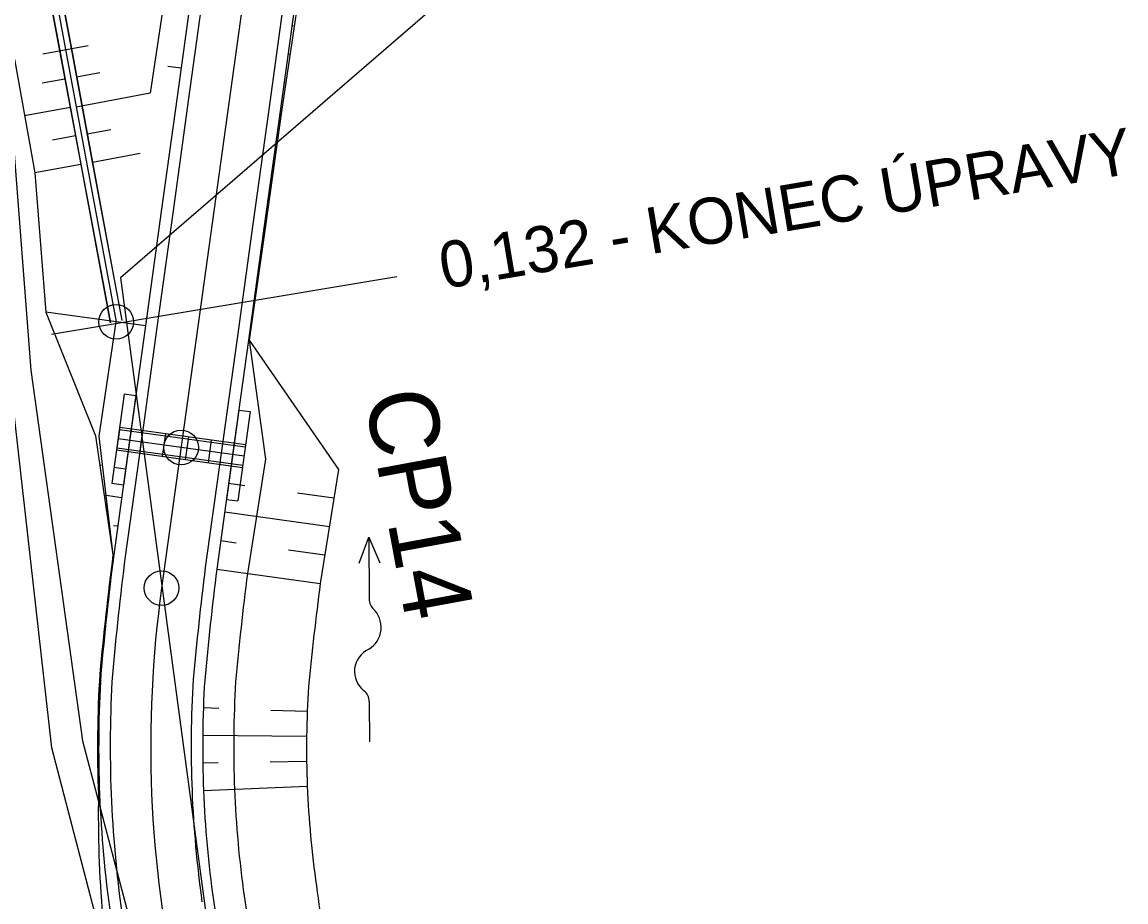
# Model space of a CAD drawing. Extents: x -495905 to -478420, y -1113297 to -1107716.
# Drawn here: x -481617.19 to -481569.44, y -1112652.71 to -1112614.65 of the extents above; entities that cross this region are included whole.
import ezdxf

# ---------------------------------------------------------------- set-up
doc = ezdxf.new("R2010")
doc.units = 0
for name, color, linetype in [('03_PC_OBJEKTY_NÁVRH_PR', 7, 'Continuous'), ('C11_HATCH_SLOPE_L', 7, 'Continuous'), ('C11_HATCH_SLOPE_R', 7, 'Continuous'), ('C11_HECTOMETRY', 7, 'Continuous'), ('C11_HLBODY', 7, 'Continuous'), ('C11_HRANA_TELESO', 7, 'Continuous'), ('C11_KORUNA', 7, 'Continuous'), ('C11_OSA', 7, 'Continuous'), ('C11_PRIKOP', 7, 'Continuous'), ('C11_VOZOVKA', 7, 'Continuous'), ('C11_ZPEVKRAJ', 7, 'Continuous'), ('CP14_HATCH_SLOPE_L', 7, 'Continuous'), ('CP14_HATCH_SLOPE_R', 7, 'Continuous'), ('CP14_HLBODY', 7, 'Continuous'), ('CP14_HRANA_TELESO', 7, 'Continuous'), ('CP14_KORUNA', 7, 'Continuous'), ('CP14_OSA', 7, 'Continuous'), ('CP14_STANICENI', 7, 'Continuous'), ('CP14_VOZOVKA', 7, 'Continuous'), ('CP14_ZPEVKRAJ', 7, 'Continuous'), ('DRENÁŽ', 7, 'Continuous'), ('Implicitní', 7, 'Continuous'), ('ODVODNĚNÍ PLOŠNÉ', 7, 'Continuous'), ('PLYN', 7, 'Continuous'), ('PROPUSTEK', 7, 'Continuous'), ('zamereni', 7, 'Continuous')]:
    doc.layers.add(name, color=color, linetype=linetype)

# ---------------------------------------------------------------- blocks, each defined once
blk = doc.blocks.new('A$C70B')
at = {"layer": 'DRENÁŽ'}
for p, q in [((0.869, 0.002), (-0.869, -0.002)), ((6.861, 0.426), (7.971, -0.002)), ((7.971, -0.002), (5.275, -0.002)), ((7.971, -0.002), (6.862, -0.478))]:
    blk.add_line(p, q, dxfattribs=at)
for centre, radius, start, end in [((2.168, -0.416), 1.055, 24.4039, 142.0836), ((0.872, 0.584), 0.582, 269.6924, 322.7901), ((4.08, 0.589), 1.109, 210.8873, 317.3707), ((5.319, -0.636), 0.636, 85.9766, 131.7248)]:
    blk.add_arc(centre, radius, start, end, dxfattribs=at)

msp = doc.modelspace()

# ---------------------------------------------------------------- linework, layer by layer
at = {"layer": 'C11_HATCH_SLOPE_L'}
for p, q in [((-481605.507, -1112614.794), (-481605.458, -1112614.801)), ((-481605.408, -1112614.808), (-481605.408, -1112614.808)), ((-481605.679, -1112616.032), (-481605.594, -1112616.044)), ((-481605.85, -1112617.271), (-481605.815, -1112617.276)), ((-481605.78, -1112617.28), (-481605.78, -1112617.28)), ((-481606.022, -1112618.509), (-481605.966, -1112618.516)), ((-481606.879, -1112624.7), (-481606.858, -1112624.702)), ((-481606.838, -1112624.705), (-481606.838, -1112624.705)), ((-481607.051, -1112625.938), (-481607.011, -1112625.943)), ((-481607.222, -1112627.176), (-481607.204, -1112627.178)), ((-481607.185, -1112627.181), (-481607.185, -1112627.181)), ((-481607.394, -1112628.414), (-481607.359, -1112628.419)), ((-481608.252, -1112634.605), (-481607.555, -1112634.702)), ((-481605.277, -1112635.017), (-481603.695, -1112635.236)), ((-481608.423, -1112635.843), (-481603.892, -1112636.471)), ((-481608.595, -1112637.081), (-481607.921, -1112637.174)), ((-481605.668, -1112637.486), (-481604.089, -1112637.705)), ((-481608.766, -1112638.32), (-481604.287, -1112638.94)), ((-481609.344, -1112644.308), (-481608.674, -1112644.332)), ((-481606.428, -1112644.412), (-481604.85, -1112644.467)), ((-481609.371, -1112645.502), (-481604.877, -1112645.548)), ((-481606.452, -1112646.653), (-481604.877, -1112646.63)), ((-481609.368, -1112646.695), (-481608.698, -1112646.686)), ((-481609.336, -1112647.889), (-481604.85, -1112647.711))]:
    msp.add_line(p, q, dxfattribs=at)
at = {"layer": 'C11_HATCH_SLOPE_R'}
for p, q in [((-481610.308, -1112616.653), (-481610.886, -1112616.573)), ((-481611.851, -1112627.797), (-481616.162, -1112627.2)), ((-481613.767, -1112633.841), (-481613.819, -1112633.834)), ((-481612.709, -1112633.988), (-481613.212, -1112633.918)), ((-481612.881, -1112635.226), (-481613.631, -1112635.122)), ((-481613.426, -1112636.412), (-481613.443, -1112636.41)), ((-481613.052, -1112636.464), (-481613.23, -1112636.44)), ((-481613.224, -1112637.702), (-481613.255, -1112637.698)), ((-481613.888, -1112644.148), (-481613.888, -1112644.148)), ((-481613.841, -1112644.149), (-481613.864, -1112644.148)), ((-481613.871, -1112645.455), (-481613.918, -1112645.455)), ((-481613.916, -1112646.762), (-481613.916, -1112646.762)), ((-481613.868, -1112646.761), (-481613.892, -1112646.762)), ((-481613.832, -1112648.067), (-481613.882, -1112648.069))]:
    msp.add_line(p, q, dxfattribs=at)
at = {"layer": 'C11_HECTOMETRY'}
msp.add_circle((-481610.309, -1112633.058), 0.75, dxfattribs=at)
at = {"layer": 'C11_HLBODY'}
msp.add_circle((-481611.151, -1112639.136), 0.75, dxfattribs=at)
at = {"layer": 'C11_HRANA_TELESO'}
for p, q in [((-481605.223, -1112613.572), (-481605.966, -1112618.516)), ((-481605.966, -1112618.516), (-481606.664, -1112623.468)), ((-481606.664, -1112623.468), (-481607.359, -1112628.419)), ((-481616.162, -1112627.2), (-481614.007, -1112632.546)), ((-481607.359, -1112628.419), (-481603.497, -1112634.002)), ((-481614.007, -1112632.546), (-481613.255, -1112637.698)), ((-481603.497, -1112634.002), (-481604.287, -1112638.94))]:
    msp.add_line(p, q, dxfattribs=at)
for centre, radius, start, end in [((-481457.625, -1112657.52), 156.888, 172.74144, 174.63158), ((-481475.649, -1112655.909), 129.752, 172.48521, 174.46194), ((-481561.624, -1112646.03), 52.298, 176.5048, 182.2344), ((-481561.625, -1112646.093), 43.256, 176.4138, 182.1434), ((-481561.442, -1112648.945), 52.447, 179.0426, 184.7813), ((-481561.63, -1112645.925), 43.257, 182.3665, 188.0961), ((-481561.522, -1112646.544), 43.281, 187.2643, 192.9943)]:
    msp.add_arc(centre, radius, start, end, dxfattribs=at)
at = {"layer": 'C11_KORUNA'}
for p, q in [((-481609.793, -1112612.939), (-481610.479, -1112617.891)), ((-481605.336, -1112613.556), (-481606.022, -1112618.509)), ((-481610.479, -1112617.891), (-481611.165, -1112622.844)), ((-481606.022, -1112618.509), (-481606.708, -1112623.461)), ((-481611.165, -1112622.844), (-481611.851, -1112627.797)), ((-481606.708, -1112623.461), (-481607.394, -1112628.414)), ((-481611.851, -1112627.797), (-481612.537, -1112632.749)), ((-481607.394, -1112628.414), (-481608.08, -1112633.367)), ((-481612.537, -1112632.749), (-481613.224, -1112637.702)), ((-481608.08, -1112633.367), (-481608.766, -1112638.32))]:
    msp.add_line(p, q, dxfattribs=at)
for centre, radius, start, end in [((-481457.677, -1112657.086), 156.75, 172.89648, 174.78714), ((-481466.633, -1112656.17), 143.25, 172.84189, 174.77166), ((-481561.624, -1112645.996), 52.25, 176.542, 182.2716), ((-481561.624, -1112645.996), 47.75, 176.542, 182.2716), ((-481561.624, -1112645.996), 52.25, 182.2716, 188.0012), ((-481561.624, -1112645.996), 47.75, 182.2716, 188.0012), ((-481561.624, -1112645.996), 47.75, 188.0012, 193.7307)]:
    msp.add_arc(centre, radius, start, end, dxfattribs=at)
at = {"layer": 'C11_OSA'}
msp.add_line((-481606.803, -1112607.752), (-481611.151, -1112639.136), dxfattribs=at)
msp.add_arc((-481561.624, -1112645.996), 50, 172.1135, 212.884, dxfattribs=at)
at = {"layer": 'C11_PRIKOP'}
for p, q in [((-481610.912, -1112612.784), (-481611.65, -1112617.729)), ((-481611.65, -1112617.729), (-481614.84, -1112618.33)), ((-481613.124, -1112627.62), (-481613.866, -1112632.565)), ((-481607.359, -1112628.419), (-481606.664, -1112633.563)), ((-481613.866, -1112632.565), (-481613.255, -1112637.698)), ((-481606.664, -1112633.563), (-481607.441, -1112638.503))]:
    msp.add_line(p, q, dxfattribs=at)
for centre, radius, start, end in [((-481469.295, -1112655.871), 139.233, 172.83447, 174.77734), ((-481561.623, -1112645.982), 46.41, 176.5597, 182.2893), ((-481561.625, -1112645.982), 46.409, 182.2891, 188.0187), ((-481561.626, -1112645.982), 46.407, 188.0187, 193.7482)]:
    msp.add_arc(centre, radius, start, end, dxfattribs=at)
at = {"layer": 'C11_VOZOVKA'}
for p, q in [((-481609.298, -1112613.007), (-481609.984, -1112617.96)), ((-481605.831, -1112613.487), (-481606.517, -1112618.44)), ((-481609.984, -1112617.96), (-481610.67, -1112622.913)), ((-481606.517, -1112618.44), (-481607.203, -1112623.393)), ((-481610.67, -1112622.913), (-481611.356, -1112627.865)), ((-481607.203, -1112623.393), (-481607.889, -1112628.346)), ((-481611.356, -1112627.865), (-481612.042, -1112632.818)), ((-481607.889, -1112628.346), (-481608.575, -1112633.298)), ((-481612.042, -1112632.818), (-481612.728, -1112637.771)), ((-481608.575, -1112633.298), (-481609.261, -1112638.251))]:
    msp.add_line(p, q, dxfattribs=at)
for centre, radius, start, end in [((-481458.672, -1112656.985), 155.25, 172.89081, 174.78548), ((-481465.637, -1112656.272), 144.75, 172.84839, 174.77344), ((-481561.624, -1112645.996), 51.75, 176.542, 182.2716), ((-481561.624, -1112645.996), 48.25, 176.542, 182.2716), ((-481561.624, -1112645.996), 51.75, 182.2716, 188.0012), ((-481561.624, -1112645.996), 48.25, 182.2716, 188.0012)]:
    msp.add_arc(centre, radius, start, end, dxfattribs=at)
at = {"layer": 'C11_ZPEVKRAJ'}
for p, q in [((-481609.298, -1112613.007), (-481609.984, -1112617.96)), ((-481605.831, -1112613.487), (-481606.517, -1112618.44)), ((-481609.984, -1112617.96), (-481610.67, -1112622.913)), ((-481606.517, -1112618.44), (-481607.203, -1112623.393)), ((-481610.67, -1112622.913), (-481611.356, -1112627.865)), ((-481607.203, -1112623.393), (-481607.889, -1112628.346)), ((-481611.356, -1112627.865), (-481612.042, -1112632.818)), ((-481607.889, -1112628.346), (-481608.575, -1112633.298)), ((-481612.042, -1112632.818), (-481612.728, -1112637.771)), ((-481608.575, -1112633.298), (-481609.261, -1112638.251))]:
    msp.add_line(p, q, dxfattribs=at)
for centre, radius, start, end in [((-481458.672, -1112656.985), 155.25, 172.89081, 174.78548), ((-481465.637, -1112656.272), 144.75, 172.84839, 174.77344), ((-481561.624, -1112645.996), 51.75, 176.542, 182.2716), ((-481561.624, -1112645.996), 48.25, 176.542, 182.2716), ((-481561.624, -1112645.996), 51.75, 182.2716, 188.0012), ((-481561.624, -1112645.996), 48.25, 182.2716, 188.0012)]:
    msp.add_arc(centre, radius, start, end, dxfattribs=at)
at = {"layer": 'CP14_HATCH_SLOPE_L'}
for p, q in [((-481614.826, -1112617.025), (-481613.82, -1112616.838)), ((-481614.369, -1112619.483), (-481613.346, -1112619.293)), ((-481614.14, -1112620.712), (-481612.077, -1112620.328)), ((-481610.969, -1112626.21), (-481610.969, -1112626.21))]:
    msp.add_line(p, q, dxfattribs=at)
at = {"layer": 'CP14_HATCH_SLOPE_R'}
for p, q in [((-481615.337, -1112617.12), (-481616.316, -1112617.302)), ((-481615.108, -1112618.349), (-481617.077, -1112618.715)), ((-481614.88, -1112619.578), (-481615.87, -1112619.762)), ((-481616.859, -1112619.946), (-481616.859, -1112619.946)), ((-481614.651, -1112620.807), (-481616.64, -1112621.177)), ((-481615.625, -1112627.075), (-481615.625, -1112627.075))]:
    msp.add_line(p, q, dxfattribs=at)
at = {"layer": 'CP14_HLBODY'}
msp.add_circle((-481613.12, -1112627.62), 0.75, dxfattribs=at)
at = {"layer": 'CP14_HRANA_TELESO'}
for p, q in [((-481617.515, -1112616.254), (-481616.64, -1112621.177)), ((-481616.64, -1112621.177), (-481616.162, -1112627.2))]:
    msp.add_line(p, q, dxfattribs=at)
at = {"layer": 'CP14_KORUNA'}
for p, q in [((-481616.479, -1112610.975), (-481615.565, -1112615.891)), ((-481615.968, -1112610.88), (-481615.054, -1112615.796)), ((-481615.565, -1112615.891), (-481614.651, -1112620.807)), ((-481615.054, -1112615.796), (-481614.14, -1112620.712)), ((-481614.651, -1112620.807), (-481613.737, -1112625.723)), ((-481614.14, -1112620.712), (-481613.226, -1112625.628)), ((-481613.226, -1112625.628), (-481612.866, -1112627.564)), ((-481613.737, -1112625.723), (-481613.377, -1112627.659))]:
    msp.add_line(p, q, dxfattribs=at)
at = {"layer": 'CP14_OSA'}
msp.add_line((-481625.429, -1112561.422), (-481613.12, -1112627.62), dxfattribs=at)
at = {"layer": 'CP14_STANICENI'}
for p, q in [((-481616.293, -1112616.026), (-481614.327, -1112615.661)), ((-481615.92, -1112628.16), (-481600.98, -1112625.652))]:
    msp.add_line(p, q, dxfattribs=at)
at = {"layer": 'CP14_VOZOVKA'}
for p, q in [((-481616.47, -1112610.974), (-481615.555, -1112615.889)), ((-481615.978, -1112610.882), (-481615.064, -1112615.798)), ((-481615.555, -1112615.889), (-481614.641, -1112620.805)), ((-481615.064, -1112615.798), (-481614.15, -1112620.714)), ((-481614.641, -1112620.805), (-481613.727, -1112625.721)), ((-481614.15, -1112620.714), (-481613.236, -1112625.629)), ((-481613.236, -1112625.629), (-481612.876, -1112627.566)), ((-481613.727, -1112625.721), (-481613.367, -1112627.658))]:
    msp.add_line(p, q, dxfattribs=at)
at = {"layer": 'CP14_ZPEVKRAJ'}
for p, q in [((-481616.47, -1112610.974), (-481615.555, -1112615.889)), ((-481615.978, -1112610.882), (-481615.064, -1112615.798)), ((-481615.555, -1112615.889), (-481614.641, -1112620.805)), ((-481615.064, -1112615.798), (-481614.15, -1112620.714)), ((-481614.641, -1112620.805), (-481613.727, -1112625.721)), ((-481614.15, -1112620.714), (-481613.236, -1112625.629)), ((-481613.236, -1112625.629), (-481612.876, -1112627.566)), ((-481613.727, -1112625.721), (-481613.367, -1112627.658))]:
    msp.add_line(p, q, dxfattribs=at)
at = {"layer": 'ODVODNĚNÍ PLOŠNÉ'}
msp.add_lwpolyline([(-481577.426, -1112595.058), (-481612.93, -1112625.721), (-481606.017, -1112677.167), (-481582.368, -1112709.931)], dxfattribs=at)
at = {"layer": 'PROPUSTEK'}
for p, q in [((-481612.765, -1112630.749), (-481613.3, -1112634.612)), ((-481612.27, -1112630.818), (-481612.805, -1112634.681)), ((-481612.27, -1112630.818), (-481612.765, -1112630.749)), ((-481607.813, -1112631.435), (-481608.348, -1112635.298)), ((-481607.318, -1112631.504), (-481607.853, -1112635.367)), ((-481607.813, -1112631.435), (-481607.318, -1112631.504)), ((-481612.978, -1112632.285), (-481613.088, -1112633.077)), ((-481607.53, -1112633.039), (-481612.978, -1112632.285)), ((-481607.516, -1112632.94), (-481612.964, -1112632.186)), ((-481607.585, -1112633.435), (-481613.033, -1112632.681)), ((-481611.974, -1112632.323), (-481612.111, -1112633.313)), ((-481610.983, -1112632.46), (-481611.12, -1112633.451)), ((-481609.993, -1112632.597), (-481610.13, -1112633.588)), ((-481609.002, -1112632.734), (-481609.139, -1112633.725)), ((-481607.654, -1112633.931), (-481613.101, -1112633.176)), ((-481607.64, -1112633.832), (-481613.088, -1112633.077)), ((-481608.012, -1112632.872), (-481608.149, -1112633.862)), ((-481612.805, -1112634.681), (-481613.3, -1112634.612)), ((-481608.348, -1112635.298), (-481607.853, -1112635.367))]:
    msp.add_line(p, q, dxfattribs=at)
at = {"layer": 'zamereni'}
for p, q in [((-481617.7, -1112618.09), (-481616.81, -1112629.71)), ((-481615.9, -1112646.04), (-481617.72, -1112629.92)), ((-481616.81, -1112629.71), (-481614.57, -1112645.75)), ((-481612.94, -1112657.41), (-481615.9, -1112646.04)), ((-481614.57, -1112645.75), (-481611.67, -1112656.77))]:
    msp.add_line(p, q, dxfattribs=at)

# ---------------------------------------------------------------- block references
at = {"layer": 'PLYN', "rotation": 90.17659526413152}
msp.add_blockref('A$C70B', (-481602.163, -1112644.912), dxfattribs=at)

# ---------------------------------------------------------------- texts
at = {"layer": '03_PC_OBJEKTY_NÁVRH_PR'}
msp.add_text('CP14', height=3, rotation=280.4871, dxfattribs=at).set_placement((-481602.394, -1112630.795))
at = {"layer": 'Implicitní'}
msp.add_text('0,132 - KONEC ÚPRAVY', height=2, rotation=9.5288, dxfattribs=at).set_placement((-481598.953, -1112626.199))

doc.saveas('drawing.dxf')
